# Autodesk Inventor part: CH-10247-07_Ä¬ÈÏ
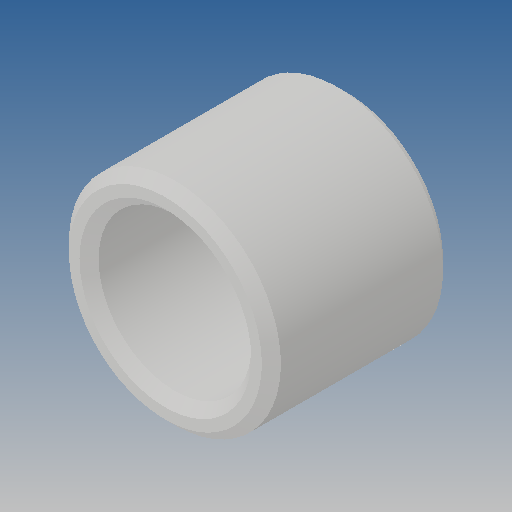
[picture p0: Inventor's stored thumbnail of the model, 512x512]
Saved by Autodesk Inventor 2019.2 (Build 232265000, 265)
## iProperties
Created: 2010-06
Part Number: CH-10247-07_Ä¬ÈÏ
Material: Ogólny
Document SubType Name: Modeling
Designer: CADENGINEERING4
Density: 1 g/cm^3
Appearance: Domyślna
Author: CADENGINEERING4
Revision Number: ÈÎºÎ
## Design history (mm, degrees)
feature "NONE"
node "Bryła1"
